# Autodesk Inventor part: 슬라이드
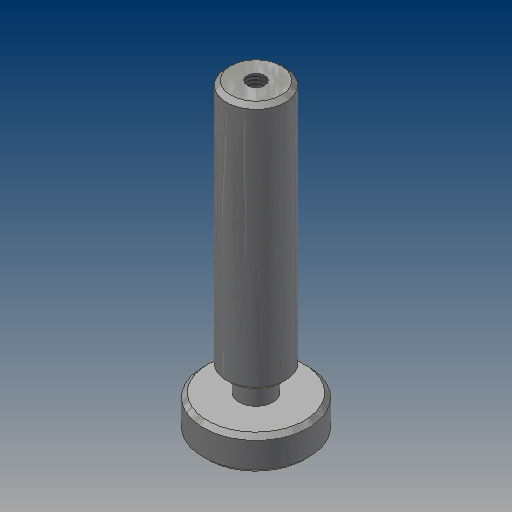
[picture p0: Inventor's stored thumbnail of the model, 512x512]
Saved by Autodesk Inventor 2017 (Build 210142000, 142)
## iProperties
Created: 2015-09
Part Number: 슬라이드
Material: 강철, 연강
Document SubType Name: Modeling
Designer: mduedu
Density: 1 g/cm^3
Appearance: 강철
Author: mduedu
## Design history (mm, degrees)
sketch "스케치1"
  geometry: C1 r 12.5 at (0, 0); 1 further point
  constraints: 1 centre point, 1 coincident
  dimensions: "d0" = 25 diameter of C1
extrude "돌출1" new body sketch "스케치1" distance "d1" = 8; taper "d2" = 0 deg
sketch "스케치2"
  geometry: C1 r 4 at (0, 0); 1 further point
  constraints: 1 centre point, 1 coincident
  dimensions: "d3" = 8 diameter of C1
extrude "돌출2" join sketch "스케치2" distance "d4" = 5; taper "d5" = 0 deg
sketch "스케치3"
  geometry: C1 r 7 at (0, 0); 1 further point
  constraints: 1 centre point, 1 coincident
  dimensions: "d6" = 14 diameter of C1
extrude "돌출3" join sketch "스케치3" distance "d7" = 59; taper "d8" = 0 deg
hole "구멍1" diameter "d11" = 4.134; stored, may be unused: countersink angle "d15" = 90 deg, drill point angle "d17" = 118 deg; dims "d9" = 10, "d10" = 10, "d12" = 9, "d13" = 4, "d14" = 2, "d16" = 12
chamfer "모따기1" distance "d18" = 1; stored, may be unused: second distance "d19" = 2, angle "d20" = 45 deg
node "솔리드1"
